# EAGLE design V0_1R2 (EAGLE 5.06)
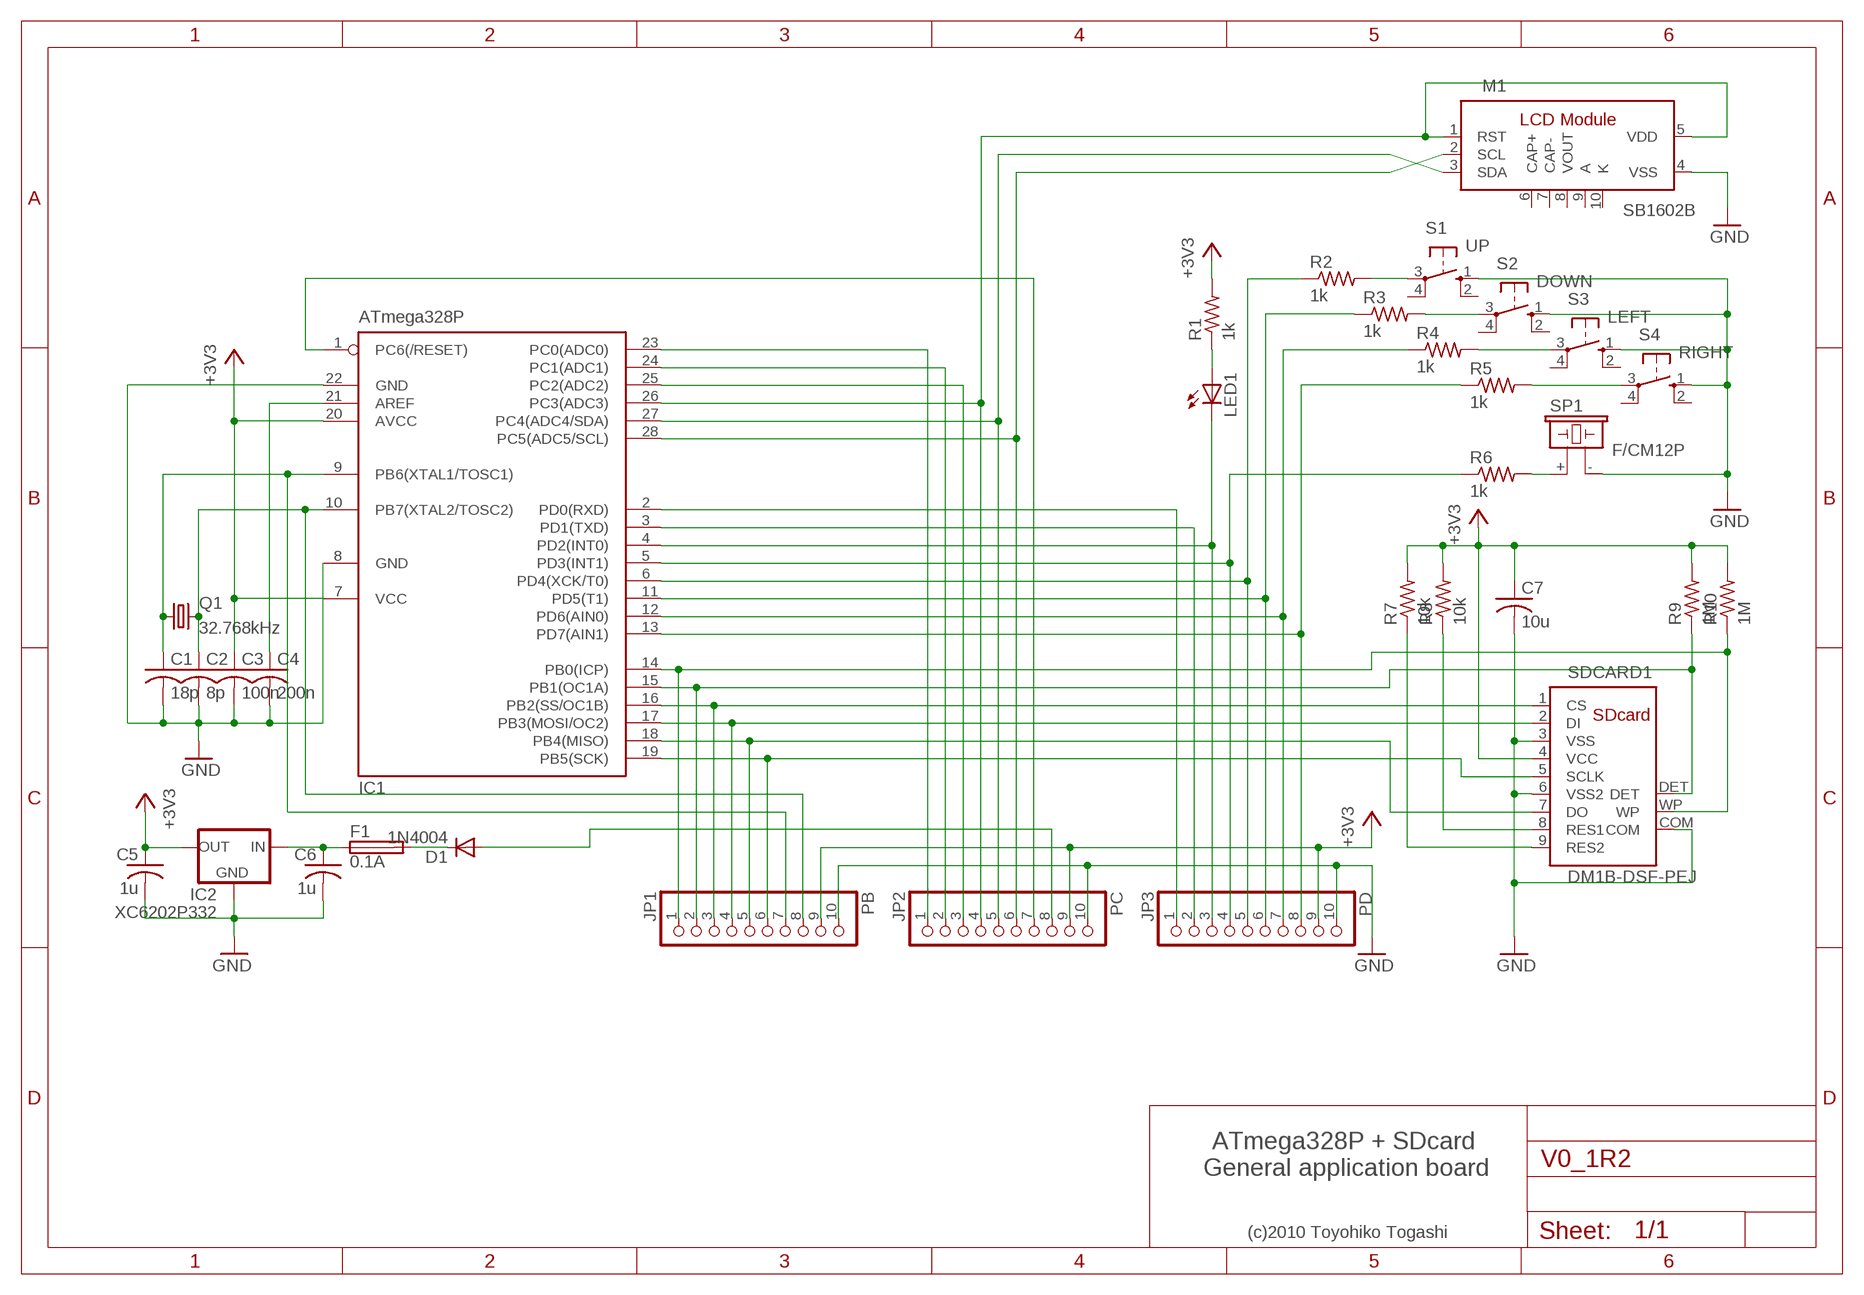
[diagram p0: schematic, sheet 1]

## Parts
C1  18p  C-US025-024X044  [C025-024X044]
C2  8p  C-US025-024X044  [C025-024X044]
C3  100n  C-US025-024X044  [C025-024X044]
C4  200n  C-US025-024X044  [C025-024X044]
C5  1u  C-US025-024X044  [C025-024X044]
C6  1u  C-US025-024X044  [C025-024X044]
C7  10u  C-US025-024X044  [C025-024X044]
D1  1N4004  DIODE-D-7.5  [D-7.5]
F1  0.1A  FUSETE5  [TE5]
IC1  ATmega328P  MEGA8-P  [DIL28-3]
IC2  XC6202P332  XC63FPL  [TO92]
JP1  PB  PINHD-1X10  [1X10]
JP2  PC  PINHD-1X10  [1X10]
JP3  PD  PINHD-1X10  [1X10]
LED1  LED3MM  [LED3MM]
M1  SB1602B  [SB1602B]
Q1  32.768kHz  CRYSTALTC26H  [TC26H]
R1  1k  R-US_0204/5  [0204/5]
R2  1k  R-US_0204/5  [0204/5]
R3  1k  R-US_0204/5  [0204/5]
R4  1k  R-US_0204/5  [0204/5]
R5  1k  R-US_0204/5  [0204/5]
R6  1k  R-US_0204/5  [0204/5]
R7  10k  R-US_0204/5  [0204/5]
R8  10k  R-US_0204/5  [0204/5]
R9  1M  R-US_0204/5  [0204/5]
R10  1M  R-US_0204/5  [0204/5]
S1  UP  10-XX  [B3F-10XX]
S2  DOWN  10-XX  [B3F-10XX]
S3  LEFT  10-XX  [B3F-10XX]
S4  RIGHT  10-XX  [B3F-10XX]
SDCARD1  DM1B-DSF-PEJ  [DM1B]
SP1  F/CM12P  [F/CM12P]

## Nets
+3V3: C3.1 C5.1 C7.1 IC1.7(VCC) IC1.20(AVCC) IC2.3(OUT) JP1.9 JP2.9 JP3.9 R1.2 R7.2 R8.2 R9.2 R10.2 SDCARD1.4(VCC)
GND: C1.2 C2.2 C3.2 C4.2 C5.2 C6.2 C7.2 IC1.8(GND) IC1.22(GND) IC2.2(GND) JP1.10 JP2.10 JP3.10 M1.4(VSS) S1.1(S) S2.1(S) S3.1(S) S4.1(S) SDCARD1.3(VSS) SDCARD1.6(VSS2) SDCARD1.COM SP1.-
N$1: IC1.16(PB2(SS/OC1B)) JP1.3 SDCARD1.1(CS)
N$2: IC1.17(PB3(MOSI/OC2)) JP1.4 SDCARD1.2(DI)
N$3: IC1.18(PB4(MISO)) JP1.5 SDCARD1.7(DO)
N$4: IC1.19(PB5(SCK)) JP1.6 SDCARD1.5(SCLK)
N$5: IC1.27(PC4(ADC4/SDA)) JP2.5 M1.3(SDA)
N$6: IC1.28(PC5(ADC5/SCL)) JP2.6 M1.2(SCL)
N$7: IC1.2(PD0(RXD)) JP3.1
N$8: IC1.3(PD1(TXD)) JP3.2
N$9: R8.1 SDCARD1.8(RES1)
N$10: R7.1 SDCARD1.9(RES2)
N$11: IC1.4(PD2(INT0)) JP3.3 LED1.K(C)
N$12: IC1.5(PD3(INT1)) JP3.4 R6.1
N$13: D1.A JP2.8
N$15: LED1.A R1.1
N$16: D1.C F1.2
N$17: R6.2 SP1.+
N$18: R2.2 S1.3(P)
N$19: IC1.24(PC1(ADC1)) JP2.2
N$20: IC1.25(PC2(ADC2)) JP2.3
N$21: C4.1 IC1.21(AREF)
N$22: IC1.14(PB0(ICP)) JP1.1 R10.1 SDCARD1.WP
N$23: IC1.15(PB1(OC1A)) JP1.2 R9.1 SDCARD1.DET
N$24: C1.1 IC1.9(PB6(XTAL1/TOSC1)) JP1.7 Q1.1
N$25: C6.1 F1.1 IC2.1(IN)
N$26: IC1.1(PC6(/RESET)) JP2.7
N$28: C2.1 IC1.10(PB7(XTAL2/TOSC2)) JP1.8 Q1.2
N$31: IC1.23(PC0(ADC0)) JP2.1
N$32: R3.2 S2.3(P)
N$33: R4.2 S3.3(P)
N$34: R5.2 S4.3(P)
N$35: IC1.26(PC3(ADC3)) JP2.4 M1.1(RST) M1.5(VDD)
N$36: IC1.13(PD7(AIN1)) JP3.8 R5.1
N$37: IC1.12(PD6(AIN0)) JP3.7 R4.1
N$38: IC1.11(PD5(T1)) JP3.6 R3.1
N$39: IC1.6(PD4(XCK/T0)) JP3.5 R2.1
Unconnected: M1.6(CAP+) M1.7(CAP-) M1.8(VOUT) S1.2(S1) S1.4(P1) S2.2(S1) S2.4(P1) S3.2(S1) S3.4(P1) S4.2(S1) S4.4(P1)

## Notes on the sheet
- ATmega328P + SDcard
- General application board
- (c)2010 Toyohiko Togashi

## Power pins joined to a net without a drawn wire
A: M1.9(A)
K: M1.10(K)

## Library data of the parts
C1-C7 = rcl:C-US: CAPACITOR, American symbol
D1 = diode:DIODE-: DIODE
F1 = fuse:FUSE: Fuse
IC1 = atmel:MEGA8-P: MICROCONTROLLER 8 Kbytes FLASH, 1 kbytes SRAM, 512 bytes EEPROM, USART, 4-channel 10 bit ADC, 2-channel 8 bit ADC Pin compatible with Atmega48, ATMega88, ATMega168 Source: avr.lbr
IC2 = v-reg:XC63FP: Positiv Voltage Regulators www.torex.co.jp/english/product/pro02/pdf/0201_xc62fp.pdf
JP1-JP3 = pinhead:PINHD-1X10: PIN HEADER
LED1 = led:LED: LED
M1 = TOG:SB1602B: Strawberry Linux Co.,Ltd. I2C LCD Module Controler: ST7032i
Q1 = crystal:CRYSTAL: CRYSTAL
R1-R10 = rcl:R-US_: RESISTOR, American symbol
S1-S4 = switch-omron:10-XX: OMRON SWITCH
SDCARD1 = TOG:DM1B-DSF-PEJ: SDcard connector reverse type HIROSE
SP1 = buzzer:F/CM12P: BUZZER

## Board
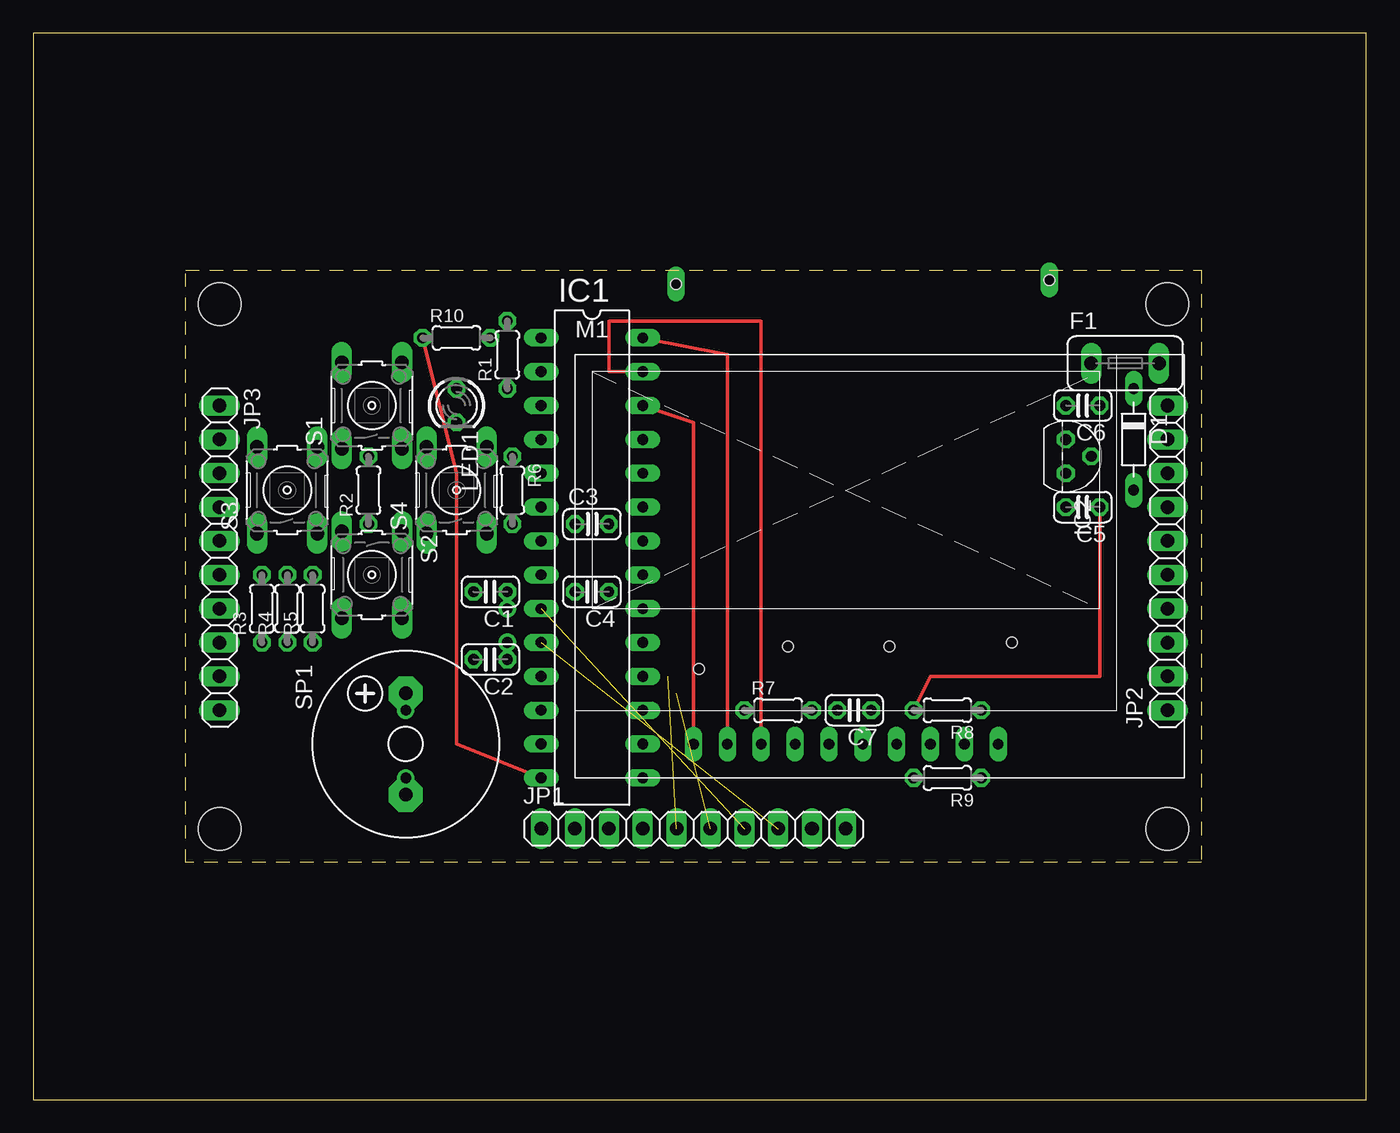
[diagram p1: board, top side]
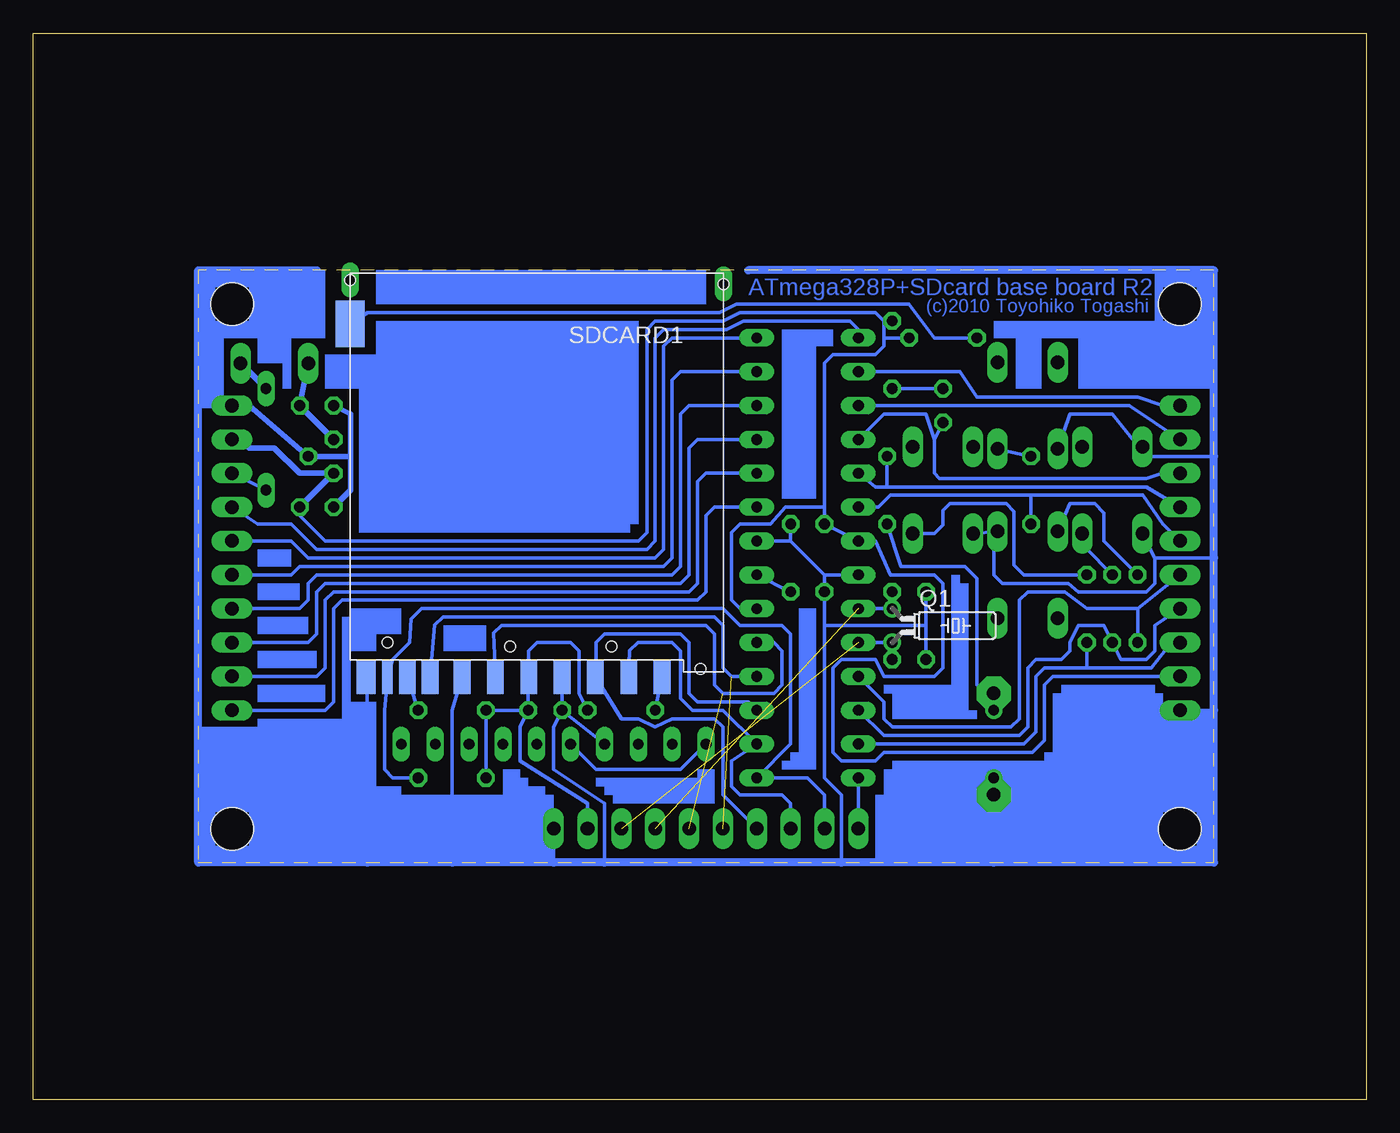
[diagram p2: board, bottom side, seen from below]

Size 100 x 80 mm. Coordinates in mm from the lower left corner, seen from the top.
Outline: 0,0 100,0 100,80 0,80 0,0
Outline: 11.43,62.23 87.63,62.23 87.63,17.78 11.43,17.78 11.43,62.23
Copper layers (1*16): Top 0.035mm / dielectric 1.5mm / Bottom 0.035mm
Design rules "default": minimum track width 10mil, minimum drill 24mil, track to track 8mil, track to pad 8mil, pad to pad 8mil, via to via 8mil, smd to smd 8mil, copper to edge 40mil, drill to drill 8mil, minimum pad ring 10mil, minimum via ring 8mil, stop-mask expansion 4mil, vias tented up to drill 0mil, thermal gap 10mil
Holes 3.2 mm at 13.97,59.69 85.09,59.69 85.09,20.32 13.97,20.32

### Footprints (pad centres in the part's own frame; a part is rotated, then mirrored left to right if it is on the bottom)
C025-024X044 = drill 0.813 octagon: 1 -1.27,0; 2 1.27,0
D-7.5 = drill 0.813 long: A 3.81,0; C -3.81,0
TE5 = drill 1.016 long: 1 -2.54,0; 2 2.54,0
DIL28-3 = drill 0.813 long: 1 -16.51,-3.81; 2 -13.97,-3.81; 3 -11.43,-3.81; 4 -8.89,-3.81; 5 -6.35,-3.81; 6 -3.81,-3.81; 7 -1.27,-3.81; 8 1.27,-3.81; 9 3.81,-3.81; 10 6.35,-3.81; 11 8.89,-3.81; 12 11.43,-3.81; 13 13.97,-3.81; 14 16.51,-3.81; 15 16.51,3.81; 16 13.97,3.81; 17 11.43,3.81; 18 8.89,3.81; 19 6.35,3.81; 20 3.81,3.81; 21 1.27,3.81; 22 -1.27,3.81; 23 -3.81,3.81; 24 -6.35,3.81; 25 -8.89,3.81; 26 -11.43,3.81; 27 -13.97,3.81; 28 -16.51,3.81
TO92 = drill 0.813 octagon: 1 -1.27,0; 2 0,1.905; 3 1.27,0
1X10 = drill 1.016 long: 1 -11.43,0; 2 -8.89,0; 3 -6.35,0; 4 -3.81,0; 5 -1.27,0; 6 1.27,0; 7 3.81,0; 8 6.35,0; 9 8.89,0; 10 11.43,0
LED3MM = drill 0.813 octagon: A -1.27,0; K 1.27,0
SB1602B = drill 0.8 long: 1 -13.97,-12.7; 2 -11.43,-12.7; 3 -8.89,-12.7; 4 -6.35,-12.7; 5 -3.81,-12.7; 6 -1.27,-12.7; 7 1.27,-12.7; 8 3.81,-12.7; 9 6.35,-12.7; 10 8.89,-12.7
TC26H = drill 0.813 round: 1 -1.27,0; 2 1.27,0
0204/5 = drill 0.813 octagon: 1 -2.54,0; 2 2.54,0
B3F-10XX = drill 1.016 long: 1 -3.251,2.261; 2 3.251,2.261; 3 -3.251,-2.261; 4 3.251,-2.261
DM1B = smd 1.25 x 2.5: 1 -6.9,15.3; 2 -4.4,15.3; 3 -1.9,15.3; 4 0.6,15.3; 5 3.1,15.3; 6 5.6,15.3; 7 8,15.3; 8 9.7,15.3; 9 -9.4,15.3 | smd 1.4 x 2.5: COM 12.8,15.3 | smd 0.8 x 2.5: DET 11.2,15.3 | drill 0.8 pad 1.2 long: P$17 14,-14.5 | drill 0.8 pad 1.27 long: P$18 -14,-14.2 | smd 2.2 x 3.5: WP 14,-11.2 | hole 0.8: -12.3,14.7; -5.6,13; 2,13; 11.2,12.7; -14,-14.2; 14,-14.5
F/CM12P = drill 1.016 pad 2.54 octagon: + 3.81,0; - -3.81,0

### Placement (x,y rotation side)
C1  34.29,38.1 180 top
C2  34.29,33.02 180 top
C3  41.91,43.18 0 top
C4  41.91,38.1 180 top
C5  78.74,44.45 180 top
C6  78.74,52.07 180 top
C7  61.59,29.21 180 top
D1  82.55,49.53 270 top
F1  81.92,55.24 0 top
IC1  41.91,40.64 270 top
IC2  77.47,48.26 270 top
JP1  49.53,20.32 0 top
JP2  85.09,40.64 90 top
JP3  13.97,40.64 270 top
LED1  31.75,52.07 270 top
M1  63.5,39.37 0 top
Q1  35.56,35.56 270 bottom
R1  35.56,55.88 90 top
R2  25.15,45.72 90 top
R3  17.14,36.83 90 top
R4  19.05,36.83 90 top
R5  20.95,36.83 90 top
R6  35.94,45.72 270 top
R7  55.88,29.21 0 top
R8  68.58,29.21 180 top
R9  68.58,24.13 180 top
R10  31.75,57.15 0 top
S1  25.4,52.07 90 top
S2  25.4,39.37 270 top
S3  19.05,45.72 90 top
S4  31.75,45.72 90 top
SDCARD1  62.23,46.99 180 bottom
SP1  27.94,26.67 90 top

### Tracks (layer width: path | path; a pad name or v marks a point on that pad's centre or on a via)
+3V3
  Top 0.254: C5.1 80.01,31.75 67.31,31.75 R8.2
  Bottom 0.254: IC1.20 46.99,36.83 47.62,37.47 47.62,42.55 46.99,43.18 44.7,43.18 43.56,44.45 40.64,44.45 | JP3.9 23.5,31.75 24.13,31.11 24.13,26.93 25.03,26.04 36.2,26.04 36.83,25.4 39.37,25.4 40.01,26.04 40.01,32.38 39.37,33.02 36.83,33.02 36.2,31.75 32.38,31.75 31.75,32.38 31.75,38.73 32.38,39.37 35.69,39.37 36.83,41.91 IC1.7 C3.1 40.64,44.45 | 36.2,57.15 36.2,56.52 36.83,55.88 40.01,55.88 40.64,55.24 40.64,44.45 | 36.2,57.15 36.2,58.42 | 36.2,58.42 36.83,59.05 46.99,59.05 48.26,58.42 53.34,58.42 53.98,57.78 53.98,42.55 54.61,41.91 78.11,41.91 80.01,43.81 C5.1 | 36.2,57.15 R10.2 | 36.2,58.42 R1.2 | C7.1 SDCARD1.4 62.86,33.64 62.22,34.29 59.69,34.29 59.05,33.66 59.05,30.48 R7.2 | C7.1 R8.2 R9.2 | JP1.9 58.42,22.23 63.5,25.4 63.5,27.94 C7.1
  Bottom 0.406: JP2.9 83.82,48.9 81.92,48.9 80.01,46.99 IC2.3 C5.1
GND
  Bottom 0.254: 74.93,17.78 74.93,29.21 SDCARD1.COM | 11.43,29.21 JP3.10 | 33.02,35.56 C2.2 | 33.02,35.56 C1.2 | 11.43,40.64 15.88,40.64 | 60.96,17.78 JP1.10 | 15.88,40.64 S3.1 | 15.88,40.64 15.88,38.73 16.51,38.1 21.59,38.1 22.35,38.73 27.3,38.73 27.94,39.37 27.94,41.91 S2.1 S4.1 | 40.64,39.37 IC1.8 | 40.64,39.37 43.18,41.91 | 43.18,41.91 IC1.22 | 43.18,41.91 C3.2 | 40.64,39.37 C4.2 40.64,35.56 | 40.64,35.56 40.64,24.13 39.37,22.86 39.37,17.78 | 40.64,35.56 33.02,35.56 | C7.2 SDCARD1.3 | C7.2 M1.4 | 57.15,17.78 57.15,22.23 60.96,24.77 60.96,27.94 C7.2 | 27.94,17.78 SP1.- | SDCARD1.6 68.58,29.21 68.58,17.78 | S1.1 22.23,51.44 19.05,51.44 16.51,48.26 11.43,48.26
  Bottom 0.406: 76.2,48.26 76.2,45.72 C5.2 | 76.2,48.26 76.2,51.44 C6.2 | 87.63,52.07 JP2.10 83.82,52.07 IC2.2 76.2,48.26
  Bottom 0.61: 46.35,62.23 11.43,62.23 11.43,48.26 11.43,40.64 11.43,29.21 11.43,17.78 27.94,17.78 39.37,17.78 57.15,17.78 60.96,17.78 68.58,17.78 74.93,17.78 87.63,17.78 87.63,52.07 87.63,62.23 78.74,62.23
N$1
  Bottom 0.254: SDCARD1.1 55.27,33.67 54.63,34.29 52.07,34.29 51.44,33.66 51.44,30.11 50.54,29.21 48.26,29.21 IC1.16 47.62,25.4 47.62,23.5 46.99,22.86 43.81,22.86 43.18,22.23 JP1.3
N$2
  Bottom 0.254: IC1.17 46.35,29.84 50.16,29.84 50.8,30.48 50.8,34.29 51.44,34.92 57.16,34.92 57.79,34.3 SDCARD1.2 55.88,28.57 54.61,28.57 53.34,27.94 52.07,28.57 48.9,28.57 48.26,27.94 48.26,22.86 JP1.4
N$3  (1 unrouted)
  Bottom 0.254: IC1.18 47.62,31.75 48.26,32.38 48.26,35.56 48.9,36.2 69.27,36.2 69.9,35.61 SDCARD1.7
N$4  (1 unrouted)
  Bottom 0.254: IC1.19 44.45,34.29 43.81,33.66 43.81,31.11 44.45,30.48 48.26,30.48 48.9,31.11 48.9,34.92 49.53,35.56 64.86,35.56 65.48,35.02 SDCARD1.5
N$5
  Top 0.254: M1.3 54.61,58.42 43.18,58.42 43.18,54.61 IC1.27
  Bottom 0.254: JP2.5 80.64,39.37 80.01,40.01 52.7,40.01 52.07,40.64 52.07,53.98 51.44,54.61 IC1.27
N$6
  Top 0.254: M1.2 52.07,55.88 IC1.28
  Bottom 0.254: JP2.6 80.64,41.91 79.38,40.64 53.34,40.64 52.7,41.27 52.7,56.52 52.07,57.15 IC1.28
N$7
  Bottom 0.254: IC1.2 30.48,54.61 29.21,52.7 17.14,52.7 15.24,52.07 JP3.1
N$8
  Bottom 0.254: JP3.2 17.78,52.07 IC1.3
N$9
  Bottom 0.254: R8.1 SDCARD1.8
N$10
  Bottom 0.254: SDCARD1.9 R7.1
N$11
  Bottom 0.254: IC1.4 36.2,51.44 33.02,51.44 32.38,49.53 | 32.38,49.53 32.38,46.99 32,46.61 16.51,46.61 15.24,46.99 JP3.3 | 32.38,49.53 LED1.K
N$12
  Bottom 0.254: 35.94,45.97 16.51,45.97 JP3.4 | 35.94,45.97 36.83,45.97 IC1.5 | 35.94,45.97 R6.1
N$13
  Bottom 0.254: D1.A JP2.8
N$15
  Bottom 0.254: LED1.A R1.1
N$16
  Bottom 0.406: F1.2 D1.C
N$17
  Bottom 0.254: SP1.+ 28.57,30.48 29.21,31.11 29.21,39.11 30.11,40.01 34.92,40.01 R6.2
N$18
  Bottom 0.254: R2.2 S1.3
N$19
  Bottom 0.254: JP2.2 78.74,31.75 78.11,32.38 78.11,37.47 77.47,38.1 50.8,38.1 50.16,38.73 50.16,46.35 49.53,46.99 IC1.24
N$20
  Bottom 0.254: JP2.3 79.38,34.29 78.74,34.92 78.74,38.1 78.11,38.73 51.44,38.73 50.8,39.37 50.8,48.9 50.16,49.53 IC1.25
N$21
  Bottom 0.254: C4.1 IC1.21
N$22
  Top 0.254: R10.1 31.75,46.99 31.75,26.67 IC1.14
  Bottom 0.254: JP1.1 IC1.14 | R10.1 32.38,57.15 34.29,59.69 47.24,59.69 48.51,59.05 74.93,59.05 SDCARD1.WP
N$23
  Bottom 0.254: JP1.2 40.64,22.86 41.91,24.13 IC1.15 43.18,26.67 43.18,34.92 43.81,35.56 46.99,35.56 48.26,36.83 70.85,36.83 71.66,36.07 71.75,34.29 73.03,33.02 SDCARD1.DET 73.66,29.21 73.66,24.77 73.03,24.13 R9.1
N$24  (1 unrouted)
  Bottom 0.254: IC1.9 Q1.1 C1.1
N$25
  Bottom 0.406: IC2.1 C6.1 F1.1
N$26
  Bottom 0.254: JP2.7 83.19,43.18 80.64,43.18 78.74,41.27 53.98,41.27 53.34,41.91 53.34,57.15 52.7,57.78 48.01,57.78 46.74,58.42 38.73,58.42 38.1,57.78 IC1.1
N$28  (1 unrouted)
  Bottom 0.254: IC1.10 Q1.2 C2.1
N$29  (via drill 0.8 pad 1.27)
  other vias: 27.94,24.13
N$30  (via drill 0.8 pad 1.27)
  other vias: 27.94,29.21
N$31
  Bottom 0.254: IC1.23 48.9,44.45 49.53,43.81 49.53,38.1 50.16,37.47 76.83,37.47 77.47,36.83 77.47,29.84 78.11,29.21 JP2.1
N$32
  Bottom 0.254: R3.2 19.68,41.91 19.68,44.02 20.37,44.7 22.23,44.7 S2.3
N$33
  Bottom 0.254: R4.2 21.08,41.4 S3.3
N$34
  Bottom 0.254: S4.3 32.39,42.47 31.75,43.11 31.75,44.2 31.24,44.7 26.98,44.7 26.42,44.14 26.42,40.11 25.68,39.37 R5.2
N$35
  Top 0.254: M1.1 49.53,50.8 IC1.26
  Bottom 0.254: JP2.4 80.01,36.83 79.38,37.47 79.38,38.73 78.74,39.37 52.07,39.37 51.44,40.01 51.44,51.44 50.8,52.07 IC1.26 | M1.1 51.44,24.77 57.78,24.77 M1.5
N$36
  Bottom 0.254: JP3.8 14.61,34.29 16.13,32.38 20.95,32.38 | 20.95,32.38 24.13,32.38 24.77,31.75 24.77,27.57 25.66,26.67 IC1.13 | 20.95,32.38 R5.1
N$37
  Bottom 0.254: JP3.7 15.88,35.56 15.88,33.66 16.51,33.02 18.41,33.02 R4.1 19.68,35.56 21.59,35.56 22.23,34.29 22.23,33.66 22.86,33.02 24.77,33.02 25.4,32.38 25.4,27.94 26.04,27.3 36.2,27.3 IC1.12
N$38
  Bottom 0.254: R3.1 17.14,36.83 | 17.14,36.83 JP3.6 | IC1.11 36.2,29.84 36.2,28.57 35.56,27.94 26.67,27.94 26.04,28.57 26.04,37.47 25.4,38.1 22.61,38.1 20.95,36.83 17.14,36.83
N$39
  Bottom 0.254: IC1.6 36.58,44.45 35.69,45.34 25.15,45.34 | JP3.5 15.24,43.18 16.76,45.34 25.15,45.34 | 25.15,45.34 R2.1
(copper drawn outside any net)
  shapes: Bottom area x63

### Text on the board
Bottom: ATmega328P+SDcard base board R2 | (c)2010 Toyohiko Togashi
